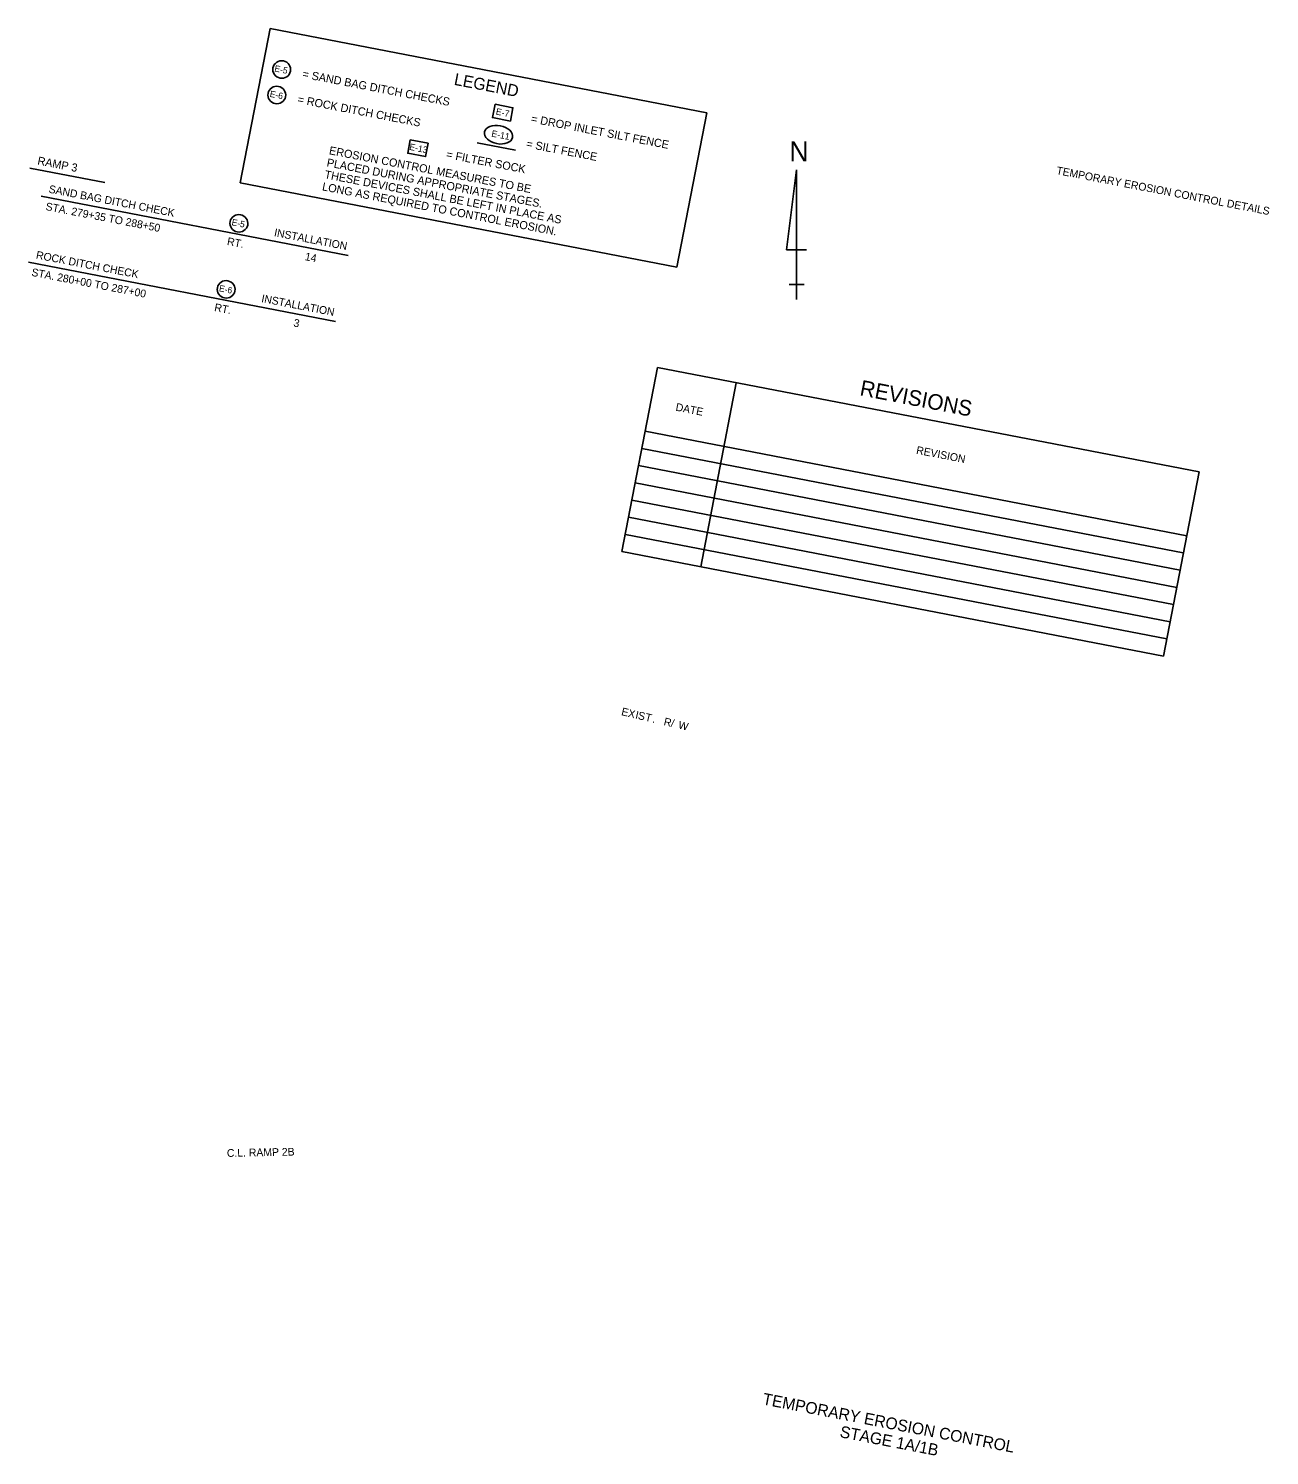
# Model space of a CAD drawing. Extents: x 610486 to 612199, y 419003 to 420102.
# Drawn here: x 611242 to 612199, y 419003 to 420102 of the extents above; entities that cross this region are included whole.
import ezdxf

# ---------------------------------------------------------------- set-up
doc = ezdxf.new("R2010")
doc.units = 0
for name, color, linetype in [('Plan Notes', 7, 'Continuous'), ('R_Draft', 7, 'Continuous'), ('R_Island', 7, 'Continuous'), ('R_Opt1 Proposed Rural', 7, 'Continuous'), ('X_Phi Angle_SB', 7, 'Continuous')]:
    doc.layers.add(name, color=color, linetype=linetype)

msp = doc.modelspace()

# ---------------------------------------------------------------- linework, layer by layer
at = {"layer": 'Plan Notes'}
msp.add_lwpolyline([(611588.1, 420014.4), (611617.7, 420008.7)], dxfattribs=at)
at = {"layer": 'R_Island'}
for p, q in [((611243.6, 419994.9), (611301.3, 419983.8)), ((611252.3, 419973.3), (611488.9, 419927.6)), ((611242.5, 419922.4), (611479.1, 419876.7))]:
    msp.add_line(p, q, dxfattribs=at)
at = {"layer": 'R_Opt1 Proposed Rural'}
for p, q in [((611405.7, 419983.5), (611428.6, 420102.4)), ((611428.6, 420102.4), (611765.1, 420037.4)), ((611765.1, 420037.4), (611742.1, 419918.6)), ((611834.4, 419993.6), (611826.7, 419932)), ((611834.4, 419893.6), (611834.4, 419993.6)), ((611834.4, 419993.6), (611834.4, 419916.7)), ((611742.1, 419918.6), (611405.7, 419983.5)), ((611826.7, 419932), (611842.1, 419932)), ((611834.4, 419893.6), (611834.4, 419916.7)), ((611834.4, 419905.1), (611828.6, 419905.1)), ((611828.6, 419905.1), (611840.2, 419905.1)), ((611834.4, 419893.6), (611834.4, 419905.1)), ((611699.8, 419699.3), (611727.2, 419841.2)), ((611727.2, 419841.2), (612144.5, 419760.7)), ((611787.9, 419829.5), (611760.5, 419687.6)), ((611717.7, 419792.1), (612135, 419711.6)), ((611715.2, 419778.9), (612132.4, 419698.3)), ((611712.6, 419765.6), (612129.9, 419685.1)), ((612144.5, 419760.7), (612117.1, 419618.8)), ((611710, 419752.4), (612127.3, 419671.8)), ((611710, 419752.4), (612127.3, 419671.8)), ((611707.5, 419739.1), (612124.8, 419658.6)), ((611704.9, 419725.8), (612122.2, 419645.3)), ((611702.4, 419712.6), (612119.7, 419632)), ((612117.1, 419618.8), (611699.8, 419699.3))]:
    msp.add_line(p, q, dxfattribs=at)
for points in [[(611602, 420044.1), (611615.8, 420041.4), (611613.8, 420031.1), (611600, 420033.8)], [(611536.7, 420016.6), (611550.4, 420014), (611548.5, 420003.7), (611534.7, 420006.3)]]:
    msp.add_lwpolyline(points, close=True, dxfattribs=at)
for centre, major_axis, ratio in [((611437.6, 420070.8), (-6.76, 1.31), 0.97521), ((611433.8, 420051.2), (-6.76, 1.31), 0.97521), ((611604.7, 420020.6), (10.8, -2.1), 0.638788), ((611404.6, 419952.3), (-6.76, 1.31), 0.97521), ((611394.8, 419901.4), (-6.76, 1.31), 0.97521)]:
    msp.add_ellipse(centre, major_axis=major_axis, ratio=ratio, dxfattribs=at)

# ---------------------------------------------------------------- texts
at = {"layer": 'R_Draft'}
for s, rotation, p in [('E', 346.8534, (611698.9, 419573.4)), ('X', 346.8534, (611704.1, 419572.1)), ('I', 346.8534, (611709.7, 419570.8)), ('S', 346.8534, (611711.7, 419570.4)), ('T', 346.8534, (611717.2, 419569.1)), ('R', 346.8534, (611731.6, 419565.7)), ('.', 346.8534, (611722.9, 419567.7)), ('/', 346.8534, (611737.1, 419564.4)), ('W', 346.8534, (611742.8, 419563.1)), ('C.L. RAMP 2B', 1.1692, (611395.4, 419232.9))]:
    msp.add_text(s, height=6, rotation=rotation, dxfattribs=at).set_placement(p)
at = {"layer": 'R_Island'}
for s, height, p in [('RAMP 3', 6.25, (611249, 419997.7)), ('TEMPORARY EROSION CONTROL DETAILS', 6, (612034.2, 419990.3)), ('SAND BAG DITCH CHECK', 6, (611257.7, 419976)), ('STA. 279+35 TO 288+50', 6, (611255.3, 419962.6)), ('INSTALLATION ', 6, (611431.4, 419942.5)), ('RT. ', 6, (611395.1, 419935.7)), ('ROCK DITCH CHECK', 6, (611247.9, 419925.2)), ('14', 6, (611455.1, 419924)), ('STA. 280+00 TO 287+00', 6, (611244.4, 419911.9)), ('RT. ', 6, (611385.3, 419884.8)), ('INSTALLATION ', 6, (611421.6, 419891.7)), ('3', 6, (611446.3, 419872.9)), ('TEMPORARY EROSION CONTROL ', 9, (611807.6, 419042.3)), ('STAGE 1A/1B', 9, (611867.2, 419017))]:
    msp.add_text(s, height=height, rotation=349.0745, dxfattribs=at).set_placement(p)
at = {"layer": 'R_Opt1 Proposed Rural'}
for s, height, rotation, p in [('E-5', 4.88, 349.0745, (611431.7, 420069.4)), ('= SAND BAG DITCH CHECKS', 6.25, 349.0745, (611453.2, 420064.6)), ('LEGEND', 9.14, 349.0745, (611569.9, 420059.1)), ('E-6', 4.88, 349.0745, (611428.1, 420049.8)), ('= ROCK DITCH CHECKS', 6.25, 349.0745, (611449.4, 420045)), ('E-7', 5, 348.6922, (611602.3, 420036.2)), ('E-11', 5, 349.0745, (611598.9, 420019.2)), ('EROSION CONTROL MEASURES TO BE', 6.25, 349.0745, (611473.7, 420005.6)), ('E-13', 5, 348.6922, (611535.6, 420009)), ('N', 15.4, 360, (611828.8, 420000)), ('PLACED DURING APPROPRIATE STAGES. ', 6.25, 349.0745, (611471.9, 419996.3)), ('THESE DEVICES SHALL BE LEFT IN PLACE AS ', 6.25, 349.0745, (611470.2, 419987.1)), ('LONG AS REQUIRED TO CONTROL EROSION.', 6.25, 349.0745, (611468.4, 419977.8)), ('E-5', 4.88, 349.0745, (611398.7, 419950.9)), ('E-6', 4.88, 349.0745, (611389, 419900)), ('REVISIONS', 12, 349.0745, (611882.5, 419819.9)), ('DATE', 6, 349.0745, (611740.8, 419808)), ('REVISION', 6, 349.0745, (611926.2, 419774.8))]:
    msp.add_text(s, height=height, rotation=rotation, dxfattribs=at).set_placement(p)
at = {"layer": 'X_Phi Angle_SB'}
for s, p in [('= DROP INLET SILT FENCE', (611629.3, 420030.1)), ('= SILT FENCE', (611625.6, 420010.8)), ('= FILTER SOCK', (611564, 420002.6))]:
    msp.add_text(s, height=6.25, rotation=349.0745, dxfattribs=at).set_placement(p)

doc.saveas('drawing.dxf')
